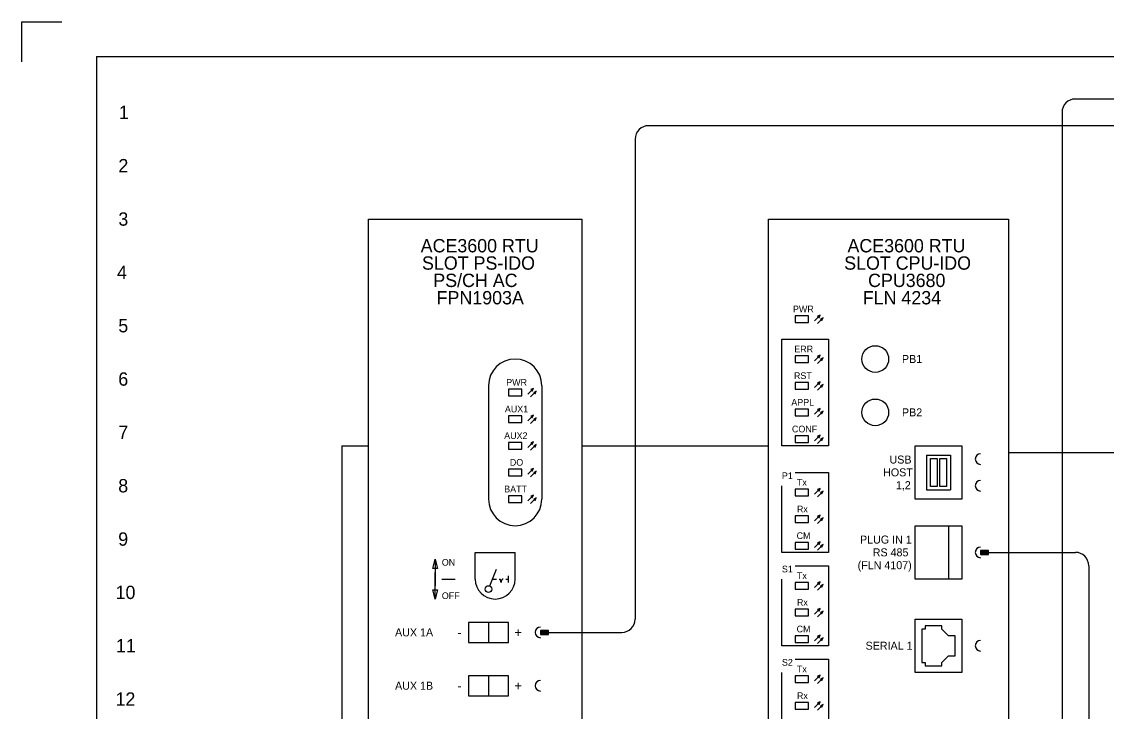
# Model space of a CAD drawing. Extents: x 0 to 841, y 0 to 594.
# Drawn here: x 0 to 406.6, y 335.4 to 594 of the extents above; entities that cross this region are included whole.
import ezdxf

# ---------------------------------------------------------------- set-up
doc = ezdxf.new("R2010")
doc.units = 0
for name, color, linetype in [('A1BORDER', 7, 'Continuous'), ('Level 1', 7, 'Continuous'), ('Level 10', 7, 'Continuous')]:
    doc.layers.add(name, color=color, linetype=linetype)

msp = doc.modelspace()

# ---------------------------------------------------------------- linework, layer by layer
at = {"layer": 'A1BORDER'}
for p, q in [((0, 594), (15, 594)), ((0, 579), (0, 594)), ((28, 581), (829, 581)), ((28, 581), (28, 15))]:
    msp.add_line(p, q, dxfattribs=at)
at = {"layer": 'Level 1'}
for p, q in [((460, 565), (395, 565)), ((390, 560), (390, 300)), ((460, 555), (235, 555)), ((230, 550), (230, 370)), ((175, 457.5), (175, 415)), ((195, 457.5), (195, 415)), ((120, 435), (120, 215)), ((120, 435), (130, 435)), ((210, 435), (280, 435)), ((339.25, 431.5), (339.25, 418.5)), ((339.25, 431.5), (348.25, 431.5)), ((348.25, 431.5), (348.25, 418.5)), ((370, 432.5), (410, 432.5)), ((339.25, 418.5), (348.25, 418.5)), ((347.5, 405), (347.5, 385)), ((170, 395), (185, 395)), ((170, 385), (170, 395)), ((185, 385), (185, 395)), ((362.5, 395), (395, 395)), ((155, 392.5), (155, 382.5)), ((155, 377.5), (155, 387.5)), ((400, 390), (400, 175)), ((157.5, 385), (162.5, 385)), ((175, 368.75), (175, 361.25)), ((337.5, 366.25), (337.5, 353.75)), ((338.75, 366.25), (337.5, 366.25)), ((345, 367.5), (338.75, 367.5)), ((338.75, 367.5), (338.75, 366.25)), ((345, 366.25), (345, 367.5)), ((345, 366.25), (347.5, 363.75)), ((197.5, 365), (225, 365)), ((350, 363.75), (347.5, 363.75)), ((350, 356.25), (350, 363.75)), ((337.5, 353.75), (338.75, 353.75)), ((338.75, 353.75), (338.75, 352.5)), ((345, 353.75), (347.5, 356.25)), ((345, 352.5), (345, 353.75)), ((347.5, 356.25), (350, 356.25)), ((338.75, 352.5), (345, 352.5)), ((175, 348.75), (175, 341.25))]:
    msp.add_line(p, q, dxfattribs=at)
for points in [[(130, 520), (210, 520), (210, 180), (130, 180)], [(280, 520), (370, 520), (370, 180), (280, 180)], [(295, 483.75), (290, 483.75), (290, 481.25), (295, 481.25)], [(285, 475), (302.5, 475), (302.5, 435), (285, 435)], [(295, 468.75), (290, 468.75), (290, 466.25), (295, 466.25)], [(187.5, 456.25), (182.5, 456.25), (182.5, 453.75), (187.5, 453.75)], [(295, 458.75), (290, 458.75), (290, 456.25), (295, 456.25)], [(295, 448.75), (290, 448.75), (290, 446.25), (295, 446.25)], [(187.5, 446.25), (182.5, 446.25), (182.5, 443.75), (187.5, 443.75)], [(187.5, 436.25), (182.5, 436.25), (182.5, 433.75), (187.5, 433.75)], [(295, 438.75), (290, 438.75), (290, 436.25), (295, 436.25)], [(335, 435), (352.5, 435), (352.5, 415), (335, 415)], [(340.75, 430.25), (343.25, 430.25), (343.25, 419.75), (340.75, 419.75)], [(344.25, 430.25), (346.75, 430.25), (346.75, 419.75), (344.25, 419.75)], [(187.5, 426.25), (182.5, 426.25), (182.5, 423.75), (187.5, 423.75)], [(187.5, 416.25), (182.5, 416.25), (182.5, 413.75), (187.5, 413.75)], [(295, 418.75), (290, 418.75), (290, 416.25), (295, 416.25)], [(295, 408.75), (290, 408.75), (290, 406.25), (295, 406.25)], [(335, 405), (352.5, 405), (352.5, 385), (335, 385)], [(295, 398.75), (290, 398.75), (290, 396.25), (295, 396.25)], [(154.13, 389), (155, 392.5), (155.87, 389)], [(295, 383.75), (290, 383.75), (290, 381.25), (295, 381.25)], [(155.87, 381), (155, 377.5), (154.13, 381)], [(295, 373.75), (290, 373.75), (290, 371.25), (295, 371.25)], [(182.5, 368.75), (167.5, 368.75), (167.5, 361.25), (182.5, 361.25)], [(335, 370), (352.5, 370), (352.5, 350), (335, 350)], [(295, 363.75), (290, 363.75), (290, 361.25), (295, 361.25)], [(182.5, 348.75), (167.5, 348.75), (167.5, 341.25), (182.5, 341.25)], [(295, 348.75), (290, 348.75), (290, 346.25), (295, 346.25)], [(295, 338.75), (290, 338.75), (290, 336.25), (295, 336.25)]]:
    msp.add_lwpolyline(points, close=True, dxfattribs=at)
for points in [[(290, 425), (302.5, 425), (302.5, 395), (285, 395), (285, 420)], [(290, 390), (302.5, 390), (302.5, 360), (285, 360), (285, 385)], [(290, 355), (302.5, 355), (302.5, 325), (285, 325), (285, 350)]]:
    msp.add_lwpolyline(points, dxfattribs=at)
for centre in [(320, 467.5), (320, 447.5)]:
    msp.add_circle(centre, 5, dxfattribs=at)
for centre, radius, start, end in [((395, 560), 5, 90, 180), ((235, 550), 5, 90, 180), ((185, 457.5), 10, 0, 180), ((185, 415), 10, 180, 0), ((395, 390), 5, 0, 90), ((177.5, 385), 7.5, 180, 0), ((225, 370), 5, 270, 360)]:
    msp.add_arc(centre, radius, start, end, dxfattribs=at)
at = {"layer": 'Level 10'}
for p, q in [((297.23, 481.86), (299.36, 483.98)), ((299.12, 483.88), (299.31, 483.88)), ((298.29, 480.8), (300.42, 482.92)), ((298.46, 483.57), (299.17, 483.57)), ((298.5, 483.43), (299.11, 483.43)), ((298.64, 483.28), (299.04, 483.28)), ((298.79, 483.73), (299.24, 483.73)), ((298.8, 483.12), (298.97, 483.12)), ((299.52, 482.51), (300.23, 482.51)), ((299.56, 482.37), (300.17, 482.37)), ((299.7, 482.22), (300.1, 482.22)), ((299.85, 482.67), (300.3, 482.67)), ((299.86, 482.06), (300.03, 482.06)), ((300.18, 482.81), (300.37, 482.81)), ((297.23, 466.86), (299.36, 468.98)), ((298.29, 465.8), (300.42, 467.92)), ((298.46, 468.57), (299.17, 468.57)), ((298.5, 468.43), (299.11, 468.43)), ((298.64, 468.28), (299.04, 468.28)), ((298.79, 468.73), (299.24, 468.73)), ((298.8, 468.12), (298.97, 468.12)), ((299.12, 468.88), (299.31, 468.88)), ((299.85, 467.67), (300.3, 467.67)), ((300.18, 467.81), (300.37, 467.81)), ((299.52, 467.51), (300.23, 467.51)), ((299.56, 467.37), (300.17, 467.37)), ((299.7, 467.22), (300.1, 467.22)), ((299.86, 467.06), (300.03, 467.06)), ((189.73, 454.36), (191.86, 456.48)), ((190.79, 453.3), (192.91, 455.42)), ((190.96, 456.07), (191.67, 456.07)), ((191, 455.93), (191.61, 455.93)), ((191.15, 455.78), (191.53, 455.78)), ((191.29, 456.23), (191.74, 456.23)), ((191.3, 455.62), (191.47, 455.62)), ((191.62, 456.38), (191.81, 456.38)), ((297.23, 456.86), (299.36, 458.98)), ((298.29, 455.8), (300.42, 457.92)), ((298.46, 458.57), (299.17, 458.57)), ((298.5, 458.43), (299.11, 458.43)), ((298.64, 458.28), (299.04, 458.28)), ((298.79, 458.73), (299.24, 458.73)), ((298.8, 458.12), (298.97, 458.12)), ((299.12, 458.88), (299.31, 458.88)), ((299.52, 457.51), (300.23, 457.51)), ((299.56, 457.37), (300.17, 457.37)), ((299.7, 457.22), (300.1, 457.22)), ((299.85, 457.67), (300.3, 457.67)), ((299.86, 457.06), (300.03, 457.06)), ((300.18, 457.81), (300.37, 457.81)), ((192.02, 455.01), (192.73, 455.01)), ((192.06, 454.87), (192.66, 454.87)), ((192.21, 454.72), (192.59, 454.72)), ((192.35, 455.17), (192.8, 455.17)), ((192.36, 454.56), (192.53, 454.56)), ((192.68, 455.31), (192.87, 455.31)), ((297.23, 446.86), (299.36, 448.98)), ((298.29, 445.8), (300.42, 447.92)), ((298.46, 448.57), (299.17, 448.57)), ((298.5, 448.43), (299.11, 448.43)), ((298.64, 448.28), (299.04, 448.28)), ((298.79, 448.73), (299.24, 448.73)), ((298.8, 448.12), (298.97, 448.12)), ((299.12, 448.88), (299.31, 448.88)), ((299.52, 447.51), (300.23, 447.51)), ((299.56, 447.37), (300.17, 447.37)), ((299.85, 447.67), (300.3, 447.67)), ((300.18, 447.81), (300.37, 447.81)), ((189.73, 444.36), (191.86, 446.48)), ((190.79, 443.3), (192.91, 445.42)), ((190.96, 446.07), (191.67, 446.07)), ((191, 445.93), (191.61, 445.93)), ((191.15, 445.78), (191.53, 445.78)), ((191.29, 446.23), (191.74, 446.23)), ((191.3, 445.62), (191.47, 445.62)), ((191.62, 446.38), (191.81, 446.38)), ((192.02, 445.01), (192.73, 445.01)), ((192.06, 444.87), (192.66, 444.87)), ((192.21, 444.72), (192.59, 444.72)), ((192.35, 445.17), (192.8, 445.17)), ((192.36, 444.56), (192.53, 444.56)), ((192.68, 445.31), (192.87, 445.31)), ((299.7, 447.22), (300.1, 447.22)), ((299.86, 447.06), (300.03, 447.06)), ((189.73, 434.36), (191.86, 436.48)), ((190.79, 433.3), (192.91, 435.42)), ((190.96, 436.07), (191.67, 436.07)), ((191, 435.93), (191.61, 435.93)), ((191.15, 435.78), (191.53, 435.78)), ((191.29, 436.23), (191.74, 436.23)), ((191.3, 435.62), (191.47, 435.62)), ((191.62, 436.38), (191.81, 436.38)), ((192.35, 435.17), (192.8, 435.17)), ((192.68, 435.31), (192.87, 435.31)), ((297.23, 436.86), (299.36, 438.98)), ((298.29, 435.8), (300.42, 437.92)), ((298.46, 438.57), (299.17, 438.57)), ((298.5, 438.43), (299.11, 438.43)), ((298.64, 438.28), (299.04, 438.28)), ((298.79, 438.73), (299.24, 438.73)), ((298.8, 438.12), (298.97, 438.12)), ((299.12, 438.88), (299.31, 438.88)), ((299.52, 437.51), (300.23, 437.51)), ((299.56, 437.37), (300.17, 437.37)), ((299.7, 437.22), (300.1, 437.22)), ((299.85, 437.67), (300.3, 437.67)), ((299.86, 437.06), (300.03, 437.06)), ((300.18, 437.81), (300.37, 437.81)), ((192.02, 435.01), (192.73, 435.01)), ((192.06, 434.87), (192.66, 434.87)), ((192.21, 434.72), (192.59, 434.72)), ((192.36, 434.56), (192.53, 434.56)), ((189.73, 424.36), (191.86, 426.48)), ((190.79, 423.3), (192.91, 425.42)), ((190.96, 426.07), (191.67, 426.07)), ((191, 425.93), (191.61, 425.93)), ((191.15, 425.78), (191.53, 425.78)), ((191.29, 426.23), (191.74, 426.23)), ((191.3, 425.62), (191.47, 425.62)), ((191.62, 426.38), (191.81, 426.38)), ((192.02, 425.01), (192.73, 425.01)), ((192.06, 424.87), (192.66, 424.87)), ((192.21, 424.72), (192.59, 424.72)), ((192.35, 425.17), (192.8, 425.17)), ((192.36, 424.56), (192.53, 424.56)), ((192.68, 425.31), (192.87, 425.31)), ((297.23, 416.86), (299.36, 418.98)), ((299.12, 418.88), (299.31, 418.88)), ((189.73, 414.36), (191.86, 416.48)), ((190.79, 413.3), (192.91, 415.42)), ((190.96, 416.07), (191.67, 416.07)), ((191, 415.93), (191.61, 415.93)), ((191.15, 415.78), (191.53, 415.78)), ((191.29, 416.23), (191.74, 416.23)), ((191.3, 415.62), (191.47, 415.62)), ((191.62, 416.38), (191.81, 416.38)), ((192.02, 415.01), (192.73, 415.01)), ((192.06, 414.87), (192.66, 414.87)), ((192.35, 415.17), (192.8, 415.17)), ((192.68, 415.31), (192.87, 415.31)), ((298.29, 415.8), (300.42, 417.92)), ((298.46, 418.57), (299.17, 418.57)), ((298.5, 418.43), (299.11, 418.43)), ((298.64, 418.28), (299.04, 418.28)), ((298.79, 418.73), (299.24, 418.73)), ((298.8, 418.12), (298.97, 418.12)), ((299.52, 417.51), (300.23, 417.51)), ((299.56, 417.37), (300.17, 417.37)), ((299.7, 417.22), (300.1, 417.22)), ((299.85, 417.67), (300.3, 417.67)), ((299.86, 417.06), (300.03, 417.06)), ((300.18, 417.81), (300.37, 417.81)), ((192.21, 414.72), (192.59, 414.72)), ((192.36, 414.56), (192.53, 414.56)), ((297.23, 406.86), (299.36, 408.98)), ((298.29, 405.8), (300.42, 407.92)), ((298.46, 408.57), (299.17, 408.57)), ((298.5, 408.43), (299.11, 408.43)), ((298.64, 408.28), (299.04, 408.28)), ((298.79, 408.73), (299.24, 408.73)), ((298.8, 408.12), (298.97, 408.12)), ((299.12, 408.88), (299.31, 408.88)), ((299.52, 407.51), (300.23, 407.51)), ((299.56, 407.37), (300.17, 407.37)), ((299.7, 407.22), (300.1, 407.22)), ((299.85, 407.67), (300.3, 407.67)), ((299.86, 407.06), (300.03, 407.06)), ((300.18, 407.81), (300.37, 407.81)), ((297.23, 396.86), (299.36, 398.98)), ((298.46, 398.57), (299.17, 398.57)), ((298.79, 398.73), (299.24, 398.73)), ((299.12, 398.88), (299.31, 398.88)), ((298.29, 395.8), (300.42, 397.92)), ((298.5, 398.43), (299.11, 398.43)), ((298.64, 398.28), (299.04, 398.28)), ((298.8, 398.12), (298.97, 398.12)), ((299.52, 397.51), (300.23, 397.51)), ((299.56, 397.37), (300.17, 397.37)), ((299.7, 397.22), (300.1, 397.22)), ((299.85, 397.67), (300.3, 397.67)), ((299.86, 397.06), (300.03, 397.06)), ((300.18, 397.81), (300.37, 397.81)), ((359.5, 395.5), (362.5, 395.5)), ((359.5, 395.25), (362.5, 395.25)), ((359.5, 395), (362.5, 395)), ((359.5, 394.75), (362.5, 394.75)), ((359.5, 394.5), (362.5, 394.5)), ((175.46, 382.41), (178, 388.75)), ((176.5, 385), (178, 385)), ((179, 385), (179.33, 385)), ((179.75, 383.75), (179.33, 385)), ((179.75, 383.75), (180.17, 385)), ((180.5, 385), (180.17, 385)), ((181.5, 385), (182.5, 385)), ((182.5, 383.75), (182.5, 386.25)), ((297.23, 381.86), (299.36, 383.98)), ((298.29, 380.8), (300.42, 382.92)), ((298.46, 383.57), (299.17, 383.57)), ((298.5, 383.43), (299.11, 383.43)), ((298.64, 383.28), (299.04, 383.28)), ((298.79, 383.73), (299.24, 383.73)), ((298.8, 383.12), (298.97, 383.12)), ((299.12, 383.88), (299.31, 383.88)), ((299.52, 382.51), (300.23, 382.51)), ((299.56, 382.37), (300.17, 382.37)), ((299.7, 382.22), (300.1, 382.22)), ((299.85, 382.67), (300.3, 382.67)), ((300.18, 382.81), (300.37, 382.81)), ((299.86, 382.06), (300.03, 382.06)), ((297.23, 371.86), (299.36, 373.98)), ((298.29, 370.8), (300.42, 372.92)), ((298.46, 373.57), (299.17, 373.57)), ((298.5, 373.43), (299.11, 373.43)), ((298.64, 373.28), (299.04, 373.28)), ((298.79, 373.73), (299.24, 373.73)), ((298.8, 373.12), (298.97, 373.12)), ((299.12, 373.88), (299.31, 373.88)), ((299.52, 372.51), (300.23, 372.51)), ((299.56, 372.37), (300.17, 372.37)), ((299.7, 372.22), (300.1, 372.22)), ((299.85, 372.67), (300.3, 372.67)), ((299.86, 372.06), (300.03, 372.06)), ((300.18, 372.81), (300.37, 372.81)), ((194.5, 365.48), (197.5, 365.48)), ((194.5, 365.18), (197.5, 365.18)), ((194.5, 364.88), (197.5, 364.88)), ((194.5, 364.58), (197.5, 364.58)), ((194.5, 364.28), (197.5, 364.28)), ((297.23, 361.86), (299.36, 363.98)), ((298.29, 360.8), (300.42, 362.92)), ((298.46, 363.57), (299.17, 363.57)), ((298.5, 363.43), (299.11, 363.43)), ((298.64, 363.28), (299.04, 363.28)), ((298.79, 363.73), (299.24, 363.73)), ((298.8, 363.12), (298.97, 363.12)), ((299.12, 363.88), (299.31, 363.88)), ((299.52, 362.51), (300.23, 362.51)), ((299.56, 362.37), (300.17, 362.37)), ((299.7, 362.22), (300.1, 362.22)), ((299.85, 362.67), (300.3, 362.67)), ((299.86, 362.06), (300.03, 362.06)), ((300.18, 362.81), (300.37, 362.81)), ((297.23, 346.86), (299.36, 348.98)), ((298.29, 345.8), (300.42, 347.92)), ((298.46, 348.57), (299.17, 348.57)), ((298.5, 348.43), (299.11, 348.43)), ((298.64, 348.28), (299.04, 348.28)), ((298.79, 348.73), (299.24, 348.73)), ((298.8, 348.12), (298.97, 348.12)), ((299.12, 348.88), (299.31, 348.88)), ((299.52, 347.51), (300.23, 347.51)), ((299.56, 347.37), (300.17, 347.37)), ((299.7, 347.22), (300.1, 347.22)), ((299.85, 347.67), (300.3, 347.67)), ((299.86, 347.06), (300.03, 347.06)), ((300.18, 347.81), (300.37, 347.81)), ((297.23, 336.86), (299.36, 338.98)), ((298.29, 335.8), (300.42, 337.92)), ((298.46, 338.57), (299.17, 338.57)), ((298.5, 338.43), (299.11, 338.43)), ((298.64, 338.28), (299.04, 338.28)), ((298.79, 338.73), (299.24, 338.73)), ((298.8, 338.12), (298.97, 338.12)), ((299.12, 338.88), (299.31, 338.88)), ((299.52, 337.51), (300.23, 337.51)), ((299.85, 337.67), (300.3, 337.67)), ((300.18, 337.81), (300.37, 337.81)), ((299.56, 337.37), (300.17, 337.37)), ((299.7, 337.22), (300.1, 337.22)), ((299.86, 337.06), (300.03, 337.06))]:
    msp.add_line(p, q, dxfattribs=at)
for points in [[(299.36, 483.98), (298.38, 483.54), (298.92, 483)], [(300.42, 482.92), (299.44, 482.48), (299.98, 481.94)], [(299.36, 468.98), (298.38, 468.54), (298.92, 468)], [(300.42, 467.92), (299.44, 467.48), (299.98, 466.94)], [(191.86, 456.48), (190.88, 456.04), (191.41, 455.5)], [(192.91, 455.42), (191.94, 454.98), (192.47, 454.44)], [(299.36, 458.98), (298.38, 458.54), (298.92, 458)], [(300.42, 457.92), (299.44, 457.48), (299.98, 456.94)], [(299.36, 448.98), (298.38, 448.54), (298.92, 448)], [(300.42, 447.92), (299.44, 447.48), (299.98, 446.94)], [(191.86, 446.48), (190.88, 446.04), (191.41, 445.5)], [(192.91, 445.42), (191.94, 444.98), (192.47, 444.44)], [(191.86, 436.48), (190.88, 436.04), (191.41, 435.5)], [(192.91, 435.42), (191.94, 434.98), (192.47, 434.44)], [(299.36, 438.98), (298.38, 438.54), (298.92, 438)], [(300.42, 437.92), (299.44, 437.48), (299.98, 436.94)], [(191.86, 426.48), (190.88, 426.04), (191.41, 425.5)], [(192.91, 425.42), (191.94, 424.98), (192.47, 424.44)], [(299.36, 418.98), (298.38, 418.54), (298.92, 418)], [(191.86, 416.48), (190.88, 416.04), (191.41, 415.5)], [(192.91, 415.42), (191.94, 414.98), (192.47, 414.44)], [(300.42, 417.92), (299.44, 417.48), (299.98, 416.94)], [(299.36, 408.98), (298.38, 408.54), (298.92, 408)], [(300.42, 407.92), (299.44, 407.48), (299.98, 406.94)], [(299.36, 398.98), (298.38, 398.54), (298.92, 398)], [(300.42, 397.92), (299.44, 397.48), (299.98, 396.94)], [(359.5, 394.25), (362.5, 394.25), (362.5, 395.75), (359.5, 395.75)], [(299.36, 383.98), (298.38, 383.54), (298.92, 383)], [(300.42, 382.92), (299.44, 382.48), (299.98, 381.94)], [(299.36, 373.98), (298.38, 373.54), (298.92, 373)], [(300.42, 372.92), (299.44, 372.48), (299.98, 371.94)], [(194.5, 364.25), (197.5, 364.25), (197.5, 365.75), (194.5, 365.75)], [(299.36, 363.98), (298.38, 363.54), (298.92, 363)], [(300.42, 362.92), (299.44, 362.48), (299.98, 361.94)], [(299.36, 348.98), (298.38, 348.54), (298.92, 348)], [(300.42, 347.92), (299.44, 347.48), (299.98, 346.94)], [(299.36, 338.98), (298.38, 338.54), (298.92, 338)], [(300.42, 337.92), (299.44, 337.48), (299.98, 336.94)]]:
    msp.add_lwpolyline(points, close=True, dxfattribs=at)
msp.add_circle((175, 381.25), 1.25, dxfattribs=at)
for centre in [(359.5, 430), (359.5, 420), (359.5, 395), (194.5, 365), (359.5, 360), (194.5, 345)]:
    msp.add_arc(centre, 2, 90, 270, dxfattribs=at)

# ---------------------------------------------------------------- texts
at = {"layer": 'Level 1'}
for s, height, p in [('1', 5, (36.41, 557.5)), ('2', 5, (36.26, 537.5)), ('3', 5, (36.25, 517.5)), ('ACE3600 RTU', 5, (149.58, 507.5)), ('ACE3600 RTU', 5, (309.58, 507.5)), ('SLOT PS-IDO', 5, (150.08, 501)), ('SLOT CPU-IDO', 5, (308.34, 501)), ('4', 5, (35.73, 497.5)), ('PS/CH AC', 5, (154.31, 494.5)), ('CPU3680', 5, (317.3, 494.5)), ('FPN1903A', 5, (155.56, 488)), ('FLN 4234', 5, (315.31, 488)), ('PWR', 2.5, (289.14, 485)), ('5', 5, (36.23, 477.5)), ('ERR', 2.5, (289.64, 470)), ('PB1', 3, (330, 466)), ('6', 5, (36.22, 457.5)), ('PWR', 2.5, (181.64, 457.5)), ('RST', 2.5, (289.51, 460)), ('APPL', 2.5, (288.52, 450)), ('AUX1', 2.5, (181.14, 447.5)), ('PB2', 3, (330, 446)), ('7', 5, (36.21, 437.5)), ('AUX2', 2.5, (180.89, 437.5)), ('CONF', 2.5, (288.76, 440)), ('USB', 3, (325.33, 428.3)), ('DO', 2.5, (183.01, 427.5)), ('P1', 2.5, (285, 422.5)), ('HOST', 3, (322.94, 423.5)), ('8', 5, (36.2, 417.5)), ('BATT', 2.5, (180.89, 417.5)), ('Tx', 2.5, (290.63, 420)), ('1,2', 3, (327.72, 418.7)), ('Rx', 2.5, (290.63, 410)), ('9', 5, (36.19, 397.5)), ('CM', 2.5, (290.51, 400)), ('PLUG IN 1', 3, (314.27, 398.3)), ('RS 485', 3, (319.05, 393.5)), ('ON', 2.5, (157.5, 390)), ('(FLN 4107)', 3, (313.38, 388.7)), ('S1', 2.5, (285, 387.5)), ('Tx', 2.5, (290.63, 385)), ('10', 5, (35.19, 377.5)), ('OFF', 2.5, (157.5, 377.5)), ('Rx', 2.5, (290.63, 375)), ('AUX 1A', 3, (139.97, 363.5)), ('+', 3.5, (184.75, 363.25)), ('CM', 2.5, (290.51, 365)), ('11', 5, (35.33, 357.5)), ('-', 3.5, (163.4, 363.25)), ('SERIAL 1', 3, (316.36, 358.5)), ('S2', 2.5, (285, 352.5)), ('Tx', 2.5, (290.63, 350)), ('AUX 1B', 3, (139.97, 343.5)), ('+', 3.5, (184.75, 343.25)), ('12', 5, (35.17, 337.5)), ('-', 3.5, (163.4, 343.25)), ('Rx', 2.5, (290.63, 340))]:
    msp.add_text(s, height=height, dxfattribs=at).set_placement(p)

doc.saveas('drawing.dxf')
